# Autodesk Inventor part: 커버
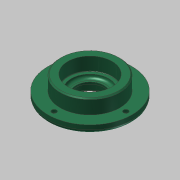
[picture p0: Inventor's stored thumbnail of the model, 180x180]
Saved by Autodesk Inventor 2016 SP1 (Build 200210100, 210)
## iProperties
Company: 한국ATC센터
Created: 2016-04
Part Number: 커버
Document SubType Name: Modeling
Designer: mdu
Density: 7.86 g/cm^3
Mass: 351.567 g
Surface Area: 161.165 cm^2
Volume: 44.7286 cm^3
Material: 강철, 연강
Appearance: 강철
Author: mdu
Revision Number: 1
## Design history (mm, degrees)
sketch "스케치1"
  geometry: C1 r 38 at (0, 0); 1 further point
  constraints: 1 centre point, 1 coincident
  dimensions: "d0" = 76 diameter of C1
extrude "돌출1" new body sketch "스케치1" distance "d1" = 7; taper "d2" = 0 deg
sketch "스케치2"
  geometry: C1 r 27 at (0, 0); 1 further point
  constraints: 1 centre point, 1 coincident
  dimensions: "d3" = 54 diameter of C1
extrude "돌출2" join sketch "스케치2" distance "d4" = 13; taper "d5" = 0 deg
sketch "스케치3"
  geometry: C1 r 20 at (0, 0); 1 further point
  constraints: 1 centre point, 1 coincident
  dimensions: "d6" = 40 diameter of C1
extrude "돌출3" join sketch "스케치3" distance "d7" = 5; taper "d8" = 0 deg
hole "구멍1" diameter "d11" = 25; stored, may be unused: countersink angle "d15" = 90 deg, drill point angle "d17" = 118 deg; dims "d9" = 10, "d10" = 10, "d12" = 6, "d13" = 32, "d14" = 8.3, "d16" = 8
hole "구멍2" diameter "d20" = 34; stored, may be unused: countersink angle "d24" = 90 deg, drill point angle "d26" = 0 deg; dims "d18" = 10, "d19" = 10, "d21" = 6, "d22" = 40, "d23" = 12, "d25" = 3
fillet "모깎기2" dims "d34" = 3
fillet "모깎기1" dims "d27" = 0.3
chamfer "모따기1" distance "d28" = 1; stored, may be unused: second distance "d29" = 2, angle "d30" = 45 deg
chamfer "모따기2" distance "d31" = 1.2; stored, may be unused: second distance "d32" = 2, angle "d33" = 30 deg
sketch "스케치4" dims "d35" = 65
  geometry: 3 further points
  constraints: 2 horizontal alignment, 1 coincident, 2 other
hole "구멍3" sketch "스케치4" at (32.5, 0) diameter "d36" = 4.5; stored, may be unused: countersink angle "d40" = 90 deg, drill point angle "d42" = 118 deg; dims "d37" = 6, "d38" = 8, "d39" = 4.4, "d41" = 13
node "솔리드1"
pattern_circular "원형 패턴1" dims angle "d44" = 360 deg
